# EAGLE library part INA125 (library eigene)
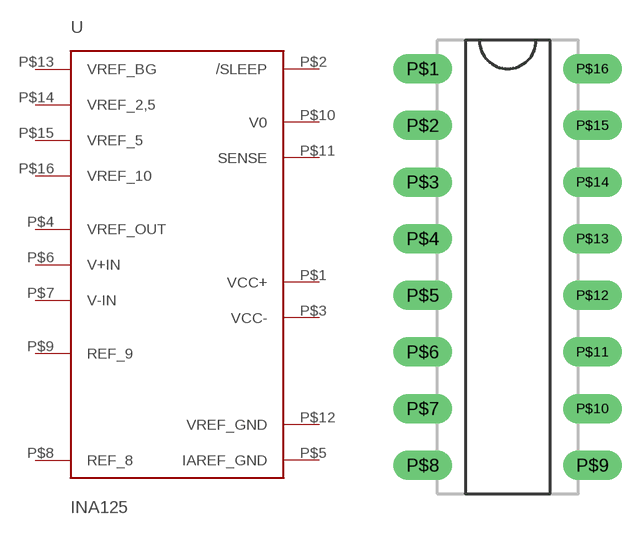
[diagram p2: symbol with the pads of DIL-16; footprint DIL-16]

Designator prefix -

## INA125  [DIL-16]
P$1  VCC+
P$2  /SLEEP
P$3  VCC-
P$4  VREF_OUT
P$5  IAREF_GND
P$6  V+IN
P$7  V-IN
P$8  REF_8
P$9  REF_9
P$10  V0
P$11  SENSE
P$12  VREF_GND
P$13  VREF_BG
P$14  VREF_2,5
P$15  VREF_5
P$16  VREF_10

## Footprint DIL-16 (pad centres in mm)
drill 0.813 long: P$1 -3.81,8.89; P$2 -3.81,6.35; P$3 -3.81,3.81; P$4 -3.81,1.27; P$5 -3.81,-1.27; P$6 -3.81,-3.81; P$7 -3.81,-6.35; P$8 -3.81,-8.89; P$9 3.81,-8.89; P$10 3.81,-6.35; P$11 3.81,-3.81; P$12 3.81,-1.27; P$13 3.81,1.27; P$14 3.81,3.81; P$15 3.81,6.35; P$16 3.81,8.89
